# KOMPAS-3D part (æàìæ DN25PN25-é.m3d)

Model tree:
1. Объединить компоненты:1  (labels: СЕНС DN25PN25-В)

Referenced files in D:\Савин\!СЕНСОР\3D для заказчика\!Новый перечень\СЕНС\3. СЕНС-В\DN25\: СЕНС DN25PN25-В.a3d
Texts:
  СЕНС DN25PN25-В
  ООО НПП Сенсор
